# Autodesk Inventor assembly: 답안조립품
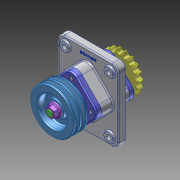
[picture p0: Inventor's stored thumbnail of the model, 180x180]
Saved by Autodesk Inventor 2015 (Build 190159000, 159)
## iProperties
Created: 2026-07
Part Number: 답안조립품
Document SubType Name: Assembly
Designer: USER
Author: USER
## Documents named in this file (12)
- C:\Users\USER\Desktop\760705V1012\답안조립품.iam
- C:\Users\USER\Desktop\760705V1012\본체.ipt
- C:\Users\USER\Desktop\760705V1012\가져온 구성요소\6각 구멍붙이 볼트 M6x16\6각 구멍붙이 볼트 M6x16.ipt
- C:\Users\USER\Desktop\760705V1012\가져온 구성요소\6각 플랜지 너트 M16\6각 플랜지 너트 M16.ipt
- C:\Users\USER\Desktop\760705V1012\가져온 구성요소\V-벨트풀리\V-벨트풀리.ipt
- C:\Users\USER\Desktop\760705V1012\가져온 구성요소\깊은 홈 볼 베어링 6206\깊은 홈 볼 베어링 6206.ipt
- C:\Users\USER\Desktop\760705V1012\가져온 구성요소\오일 실 30 45 8\오일 실 30 45 8.ipt
- C:\Users\USER\Desktop\760705V1012\가져온 구성요소\체인 스프로킷\체인 스프로킷.ipt
- C:\Users\USER\Desktop\760705V1012\가져온 구성요소\축\축.ipt
- C:\Users\USER\Desktop\760705V1012\가져온 구성요소\칼라\칼라.ipt
- C:\Users\USER\Desktop\760705V1012\가져온 구성요소\커버\커버.ipt
- C:\Users\USER\Desktop\760705V1012\가져온 구성요소\평행 키 6x6x20\평행 키 6x6x20.ipt
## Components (11 placed, 3 different names)
1. 6각 구멍붙이 볼트 M6x16:1
2. 6각 플랜지 너트 M16:1
3. V-벨트풀리:1
4. 6각 구멍붙이 볼트 M6x16:2
5. 6각 구멍붙이 볼트 M6x16:3
6. 6각 구멍붙이 볼트 M6x16:4
7. 6각 구멍붙이 볼트 M6x16:5
8. 6각 구멍붙이 볼트 M6x16:6
9. 6각 구멍붙이 볼트 M6x16:7
10. 6각 구멍붙이 볼트 M6x16:8
11. 6각 플랜지 너트 M16:2
